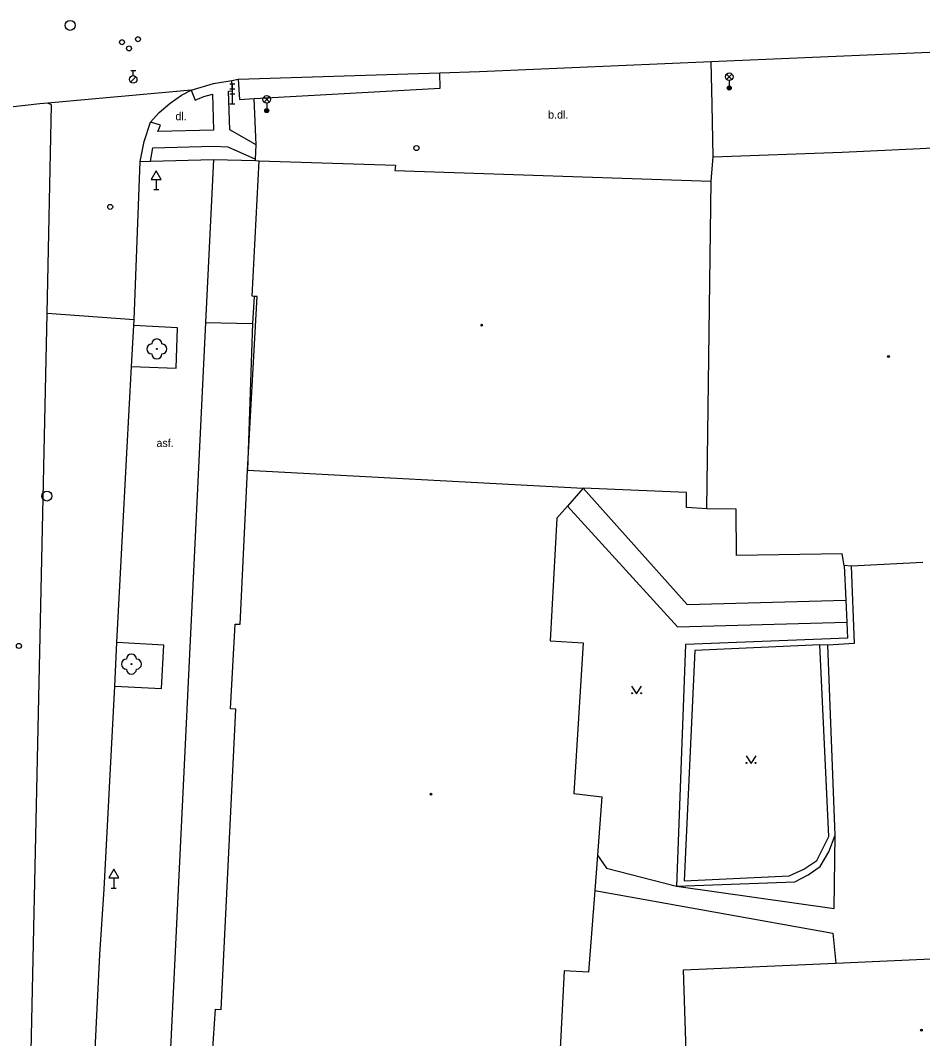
# Model space of a CAD drawing. Extents: x -599770 to -598493, y -1162076 to -1159209.
# Drawn here: x -599059.8 to -599014.8, y -1159660.9 to -1159610 of the extents above; entities that cross this region are included whole.
import ezdxf

# ---------------------------------------------------------------- set-up
doc = ezdxf.new("R2010")
doc.units = 0
doc.layers.add('Podklad', color=7, linetype='Continuous')

msp = doc.modelspace()

# ---------------------------------------------------------------- linework, layer by layer
at = {"layer": 'Podklad'}
for p, q in [((-599054.325, -1159612.552), (-599054.075, -1159612.552)), ((-599054.2, -1159612.802), (-599054.2, -1159612.552)), ((-599054.329, -1159613.126), (-599054.064, -1159612.861)), ((-599024.553, -1159612.99), (-599024.288, -1159612.725)), ((-599024.553, -1159612.725), (-599024.288, -1159612.99)), ((-599024.42, -1159613.045), (-599024.42, -1159613.42)), ((-599049.365, -1159613.21), (-599049.115, -1159613.21)), ((-599049.365, -1159613.46), (-599049.115, -1159613.46)), ((-599049.24, -1159614.21), (-599049.24, -1159613.21)), ((-599049.365, -1159613.71), (-599049.115, -1159613.71)), ((-599047.663, -1159614.12), (-599047.398, -1159613.855)), ((-599047.663, -1159613.855), (-599047.398, -1159614.12)), ((-599047.53, -1159614.175), (-599047.53, -1159614.55)), ((-599049.365, -1159614.21), (-599049.115, -1159614.21)), ((-599053.05, -1159617.991), (-599053.05, -1159618.5)), ((-599053.175, -1159618.5), (-599052.925, -1159618.5)), ((-599055.17, -1159652.891), (-599055.17, -1159653.4)), ((-599055.295, -1159653.4), (-599055.045, -1159653.4))]:
    msp.add_line(p, q, dxfattribs=at)
for points in [[(-599038.88, -1159612.66), (-599036.89, -1159612.6), (-599025.327, -1159612.1), (-599006.6, -1159611.29), (-599003.92, -1159611.177), (-598988.64, -1159610.53)], [(-599025.23, -1159616.86), (-599025.281, -1159614.242), (-599025.327, -1159612.1)], [(-599048.96, -1159612.98), (-599038.88, -1159612.66)], [(-599048.96, -1159612.98), (-599048.89, -1159613.99), (-599048.148, -1159613.948), (-599038.86, -1159613.42), (-599038.88, -1159612.66)], [(-599051.3, -1159613.53), (-599050.19, -1159613.2), (-599049.28, -1159613.04)], [(-599048.09, -1159616.98), (-599048.06, -1159616.26), (-599049.38, -1159615.51), (-599049.44, -1159613.58), (-599049.24, -1159613.56), (-599049.28, -1159613.04)], [(-599049.28, -1159613.04), (-599048.96, -1159612.98)], [(-599051.3, -1159613.53), (-599058.459, -1159614.179)], [(-599053.34, -1159615.12), (-599052.91, -1159614.64), (-599052.36, -1159614.17), (-599051.79, -1159613.78), (-599051.3, -1159613.53)], [(-599051.3, -1159613.53), (-599051.1, -1159614.02), (-599050.67, -1159613.85), (-599050.23, -1159613.72), (-599050.18, -1159615.53), (-599052.97, -1159615.6), (-599052.84, -1159615.28), (-599053.34, -1159615.12)], [(-599058.459, -1159614.179), (-599058.873, -1159614.216), (-599062.39, -1159614.61)], [(-599058.503, -1159624.689), (-599058.276, -1159614.256), (-599058.459, -1159614.179)], [(-599048.06, -1159616.26), (-599048.148, -1159613.948)], [(-599053.85, -1159617.09), (-599053.65, -1159616.1), (-599053.34, -1159615.12)], [(-599014.88, -1159616.45), (-599008.55, -1159616.09)], [(-599053.34, -1159617.08), (-599053.22, -1159616.41), (-599050.19, -1159616.33), (-599049.47, -1159616.36), (-599048.09, -1159616.98)], [(-599025.23, -1159616.86), (-599018.77, -1159616.63)], [(-599018.77, -1159616.63), (-599014.88, -1159616.45)], [(-599050.19, -1159616.99), (-599050.583, -1159625.132), (-599053.3, -1159681.44), (-599053.76, -1159690.237), (-599054.74, -1159709.09)], [(-599054.17, -1159625.28), (-599054.159, -1159625.005), (-599053.85, -1159617.09)], [(-599053.85, -1159617.09), (-599053.34, -1159617.08)], [(-599053.34, -1159617.08), (-599050.19, -1159616.99)], [(-599050.19, -1159616.99), (-599048.09, -1159617.05)], [(-599048.26, -1159623.83), (-599047.9, -1159617.06)], [(-599048.09, -1159617.05), (-599048.09, -1159616.98)], [(-599048.09, -1159617.05), (-599047.9, -1159617.06)], [(-599047.9, -1159617.06), (-599041.1, -1159617.28)], [(-599025.33, -1159618.07), (-599025.23, -1159616.86)], [(-599041.1, -1159617.28), (-599041.12, -1159617.55)], [(-599041.12, -1159617.55), (-599025.33, -1159618.07)], [(-599025.54, -1159634.45), (-599025.33, -1159618.07)], [(-599048.49, -1159632.52), (-599048, -1159623.84)], [(-599048, -1159623.84), (-599048.162, -1159623.834), (-599048.26, -1159623.83)], [(-599048.162, -1159623.834), (-599048.239, -1159625.182)], [(-599064.99, -1159695.953), (-599060.021, -1159694.564), (-599058.503, -1159624.689)], [(-599054.159, -1159625.005), (-599058.503, -1159624.689)], [(-599054.28, -1159627.34), (-599054.17, -1159625.28)], [(-599054.28, -1159627.34), (-599052.05, -1159627.42), (-599051.98, -1159625.4), (-599054.17, -1159625.28)], [(-599050.583, -1159625.132), (-599048.239, -1159625.182)], [(-599048.239, -1159625.182), (-599048.49, -1159632.52)], [(-599055.01, -1159641.13), (-599054.52, -1159631.67), (-599054.28, -1159627.34)], [(-599048.86, -1159640.22), (-599048.49, -1159632.52)], [(-599048.49, -1159632.52), (-599031.71, -1159633.42)], [(-599031.71, -1159633.42), (-599032.5, -1159634.31), (-599033.04, -1159634.91)], [(-599026.55, -1159633.64), (-599031.71, -1159633.42)], [(-599031.71, -1159633.42), (-599026.52, -1159639.23), (-599018.59, -1159639.01)], [(-599026.56, -1159634.38), (-599026.55, -1159633.64)], [(-599032.5, -1159634.31), (-599027, -1159640.35), (-599018.55, -1159640.12)], [(-599025.54, -1159634.45), (-599026.56, -1159634.38)], [(-599024.08, -1159634.46), (-599025.54, -1159634.45)], [(-599024.06, -1159636.78), (-599024.08, -1159634.46)], [(-599033.04, -1159634.91), (-599033.37, -1159641.05)], [(-599018.77, -1159636.7), (-599024.06, -1159636.78)], [(-599018.67, -1159637.28), (-599018.77, -1159636.7)], [(-599018.33, -1159637.31), (-599018.67, -1159637.28)], [(-599018.67, -1159637.28), (-599018.59, -1159639.01), (-599018.55, -1159640.12), (-599018.51, -1159640.92)], [(-599014.74, -1159637.13), (-599018.33, -1159637.31)], [(-599018.33, -1159637.31), (-599018.18, -1159641.18)], [(-599049.34, -1159644.45), (-599049.1, -1159640.21)], [(-599049.1, -1159640.21), (-599048.86, -1159640.22)], [(-599055.12, -1159643.31), (-599055.01, -1159641.13)], [(-599055.12, -1159643.31), (-599052.78, -1159643.43), (-599052.67, -1159641.26), (-599055.01, -1159641.13)], [(-599033.37, -1159641.05), (-599031.71, -1159641.14)], [(-599031.71, -1159641.14), (-599032.18, -1159648.67)], [(-599018.51, -1159640.92), (-599026.61, -1159641.23)], [(-599026.61, -1159641.23), (-599027.05, -1159653.3)], [(-599026.14, -1159641.53), (-599026.68, -1159653.04)], [(-599019.9, -1159641.24), (-599026.14, -1159641.53)], [(-599019.44, -1159650.82), (-599019.9, -1159641.24)], [(-599019.5, -1159641.26), (-599019.9, -1159641.24)], [(-599018.18, -1159641.18), (-599019.5, -1159641.26)], [(-599019.12, -1159650.76), (-599019.5, -1159641.26)], [(-599056.45, -1159668.6), (-599055.86, -1159656.72), (-599055.65, -1159653.45), (-599055.12, -1159643.31)], [(-599029.3, -1159643.315), (-599029.05, -1159643.69), (-599028.8, -1159643.315)], [(-599049.8, -1159659.47), (-599049.08, -1159644.46)], [(-599049.08, -1159644.46), (-599049.34, -1159644.45)], [(-599023.58, -1159646.795), (-599023.33, -1159647.17), (-599023.08, -1159646.795)], [(-599032.18, -1159648.67), (-599030.79, -1159648.84)], [(-599030.79, -1159648.84), (-599031.01, -1159651.76), (-599031.14, -1159653.52), (-599031.45, -1159657.61)], [(-599031.01, -1159651.76), (-599030.56, -1159652.4), (-599027.05, -1159653.3), (-599019.17, -1159654.43), (-599019.12, -1159650.76)], [(-599020.05, -1159652.03), (-599019.44, -1159650.82)], [(-599019.45, -1159651.59), (-599019.12, -1159650.76)], [(-599019.88, -1159652.33), (-599019.45, -1159651.59)], [(-599020.7, -1159652.45), (-599020.05, -1159652.03)], [(-599020.47, -1159652.74), (-599019.88, -1159652.33)], [(-599026.68, -1159653.04), (-599021.43, -1159652.79)], [(-599021.43, -1159652.79), (-599020.7, -1159652.45)], [(-599021.14, -1159653.09), (-599020.47, -1159652.74)], [(-599027.05, -1159653.3), (-599021.14, -1159653.09)], [(-599031.14, -1159653.52), (-599019.25, -1159655.66), (-599019.09, -1159657.15)], [(-599026.71, -1159657.48), (-599019.09, -1159657.15), (-599012.5, -1159656.86), (-599004.21, -1159656.5)], [(-599032.67, -1159657.53), (-599033.01, -1159664.35)], [(-599031.45, -1159657.61), (-599032.67, -1159657.53)], [(-599026.48, -1159664.65), (-599026.71, -1159657.48)], [(-599050.38, -1159663.85), (-599050.09, -1159659.46)], [(-599050.09, -1159659.46), (-599049.8, -1159659.47)]]:
    msp.add_lwpolyline(points, dxfattribs=at)
for points in [[(-599053.3, -1159617.991), (-599052.8, -1159617.991), (-599053.05, -1159617.558)], [(-599055.42, -1159652.891), (-599054.92, -1159652.891), (-599055.17, -1159652.458)]]:
    msp.add_lwpolyline(points, close=True, dxfattribs=at)
for centre, radius in [((-599057.35, -1159610.29), 0.25), ((-599054.76, -1159611.13), 0.125), ((-599053.96, -1159610.98), 0.125), ((-599054.41, -1159611.44), 0.125), ((-599054.2, -1159612.99), 0.188), ((-599024.42, -1159612.858), 0.188), ((-599024.42, -1159613.42), 0.1), ((-599024.42, -1159613.42), 0.0723), ((-599024.42, -1159613.42), 0.0438), ((-599047.53, -1159613.988), 0.188), ((-599047.53, -1159614.55), 0.1), ((-599047.53, -1159614.55), 0.0723), ((-599047.53, -1159614.55), 0.0438), ((-599040.05, -1159616.42), 0.125), ((-599055.35, -1159619.36), 0.125), ((-599036.79, -1159625.27), 0.045), ((-599036.79, -1159625.27), 0.0199), ((-599053.02, -1159626.46), 0.025), ((-599016.46, -1159626.84), 0.045), ((-599016.46, -1159626.84), 0.0199), ((-599058.51, -1159633.81), 0.25), ((-599059.91, -1159641.3), 0.125), ((-599054.29, -1159642.21), 0.025), ((-599029.275, -1159643.665), 0.025), ((-599028.825, -1159643.665), 0.025), ((-599023.555, -1159647.145), 0.025), ((-599023.105, -1159647.145), 0.025), ((-599039.32, -1159648.71), 0.045), ((-599039.32, -1159648.71), 0.0199), ((-599014.82, -1159660.5), 0.045), ((-599014.82, -1159660.5), 0.0199)]:
    msp.add_circle(centre, radius, dxfattribs=at)
for centre, start, end in [((-599053.27, -1159626.46), 90, 270), ((-599053.02, -1159626.21), 0, 180), ((-599052.77, -1159626.46), 270, 90), ((-599053.02, -1159626.71), 180, 0), ((-599054.54, -1159642.21), 90, 270), ((-599054.29, -1159641.96), 0, 180), ((-599054.04, -1159642.21), 270, 90), ((-599054.29, -1159642.46), 180, 0)]:
    msp.add_arc(centre, 0.25, start, end, dxfattribs=at)

# ---------------------------------------------------------------- texts
for s, p in [('dl.', (-599052.09, -1159615.03)), ('b.dl.', (-599033.47, -1159614.95)), ('asf.', (-599053.04, -1159631.36))]:
    msp.add_text(s, height=0.4, dxfattribs=at).set_placement(p)

doc.saveas('drawing.dxf')
